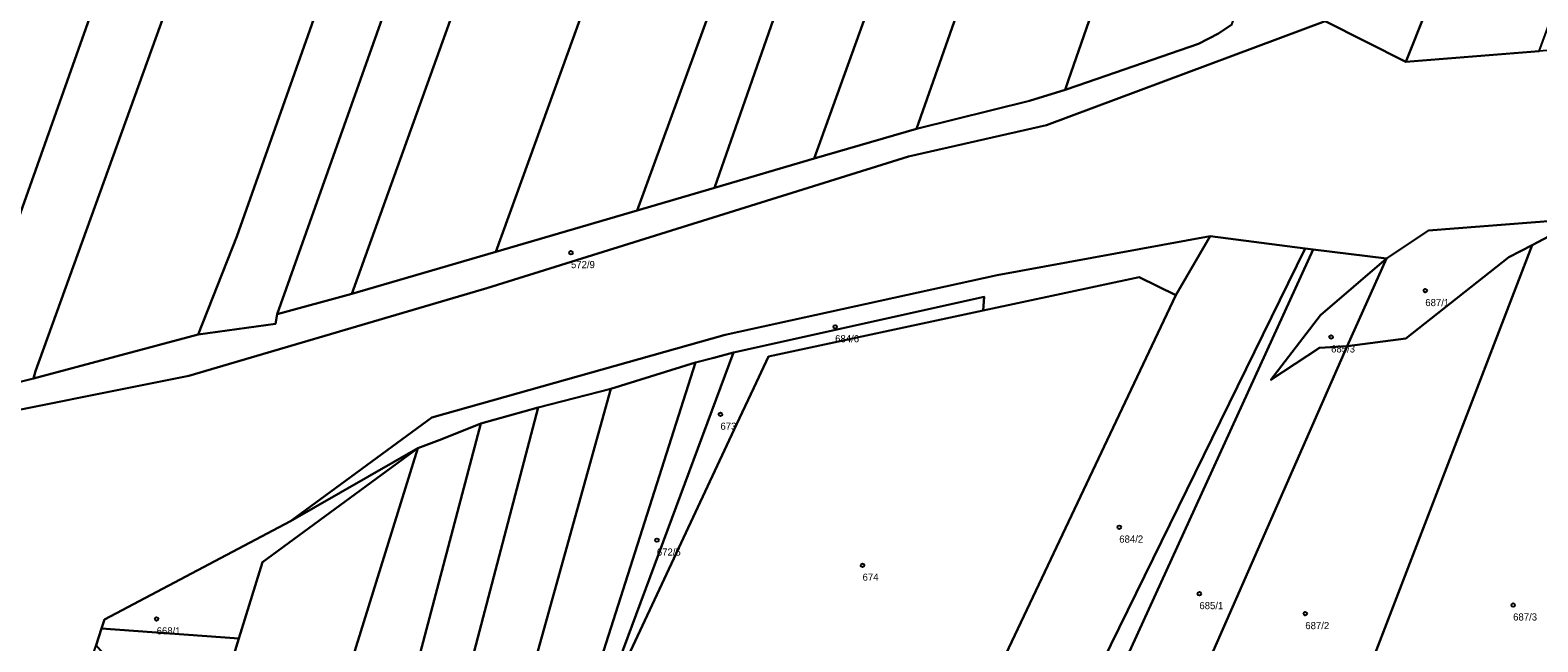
# Model space of a CAD drawing. Extents: x -587171 to -555306, y -1167727 to -1074732.
# Drawn here: x -585851.6 to -585640.5, y -1165891.7 to -1165806 of the extents above; entities that cross this region are included whole.
import ezdxf

# ---------------------------------------------------------------- set-up
doc = ezdxf.new("R2010")
doc.units = 0
doc.layers.add('Definiční body', color=7, linetype='Continuous')
doc.layers.add('Polygon parcely', color=7, linetype='Continuous')

msp = doc.modelspace()

# ---------------------------------------------------------------- linework, layer by layer
at = {"layer": 'Definiční body'}
for centre in [(-585775.86, -1165837.15), (-585656.24, -1165842.47), (-585738.87, -1165847.53), (-585669.43, -1165848.96), (-585754.93, -1165859.79), (-585699.09, -1165875.6), (-585763.83, -1165877.41), (-585735.03, -1165880.94), (-585687.87, -1165884.92), (-585643.94, -1165886.51), (-585833.87, -1165888.46), (-585673.04, -1165887.72)]:
    msp.add_circle(centre, 0.25, dxfattribs=at)
at = {"layer": 'Polygon parcely'}
for points in [[(-585806.55, -1165842.92), (-585765.04, -1165727.45), (-585762.67, -1165720.95), (-585772.03, -1165717.89), (-585777.4, -1165733.66), (-585781.47, -1165745.63), (-585816.98, -1165845.76)], [(-585816.63, -1165758.9), (-585850.85, -1165853.73), (-585851.12, -1165854.77), (-585828.07, -1165848.6), (-585822.63, -1165834.89), (-585798.71, -1165767.13), (-585790.21, -1165742.75), (-585788.68, -1165738.36), (-585788.25, -1165730.08), (-585803.96, -1165725.58), (-585805.43, -1165729.45), (-585806.58, -1165732.48), (-585811.69, -1165745.9)], [(-585763.04, -1165728.17), (-585765.04, -1165727.45), (-585806.55, -1165842.92), (-585786.4, -1165837.02), (-585753.5, -1165746.14), (-585751.18, -1165739.84), (-585749.24, -1165734.56), (-585759.82, -1165730.24), (-585760.44, -1165731.91), (-585763.85, -1165730.63)], [(-585833.2, -1165737.92), (-585839.78, -1165755.36), (-585870.01, -1165849.22), (-585861.55, -1165855.81), (-585821.32, -1165742.33)], [(-585723.27, -1165738.23), (-585729.7, -1165753.51), (-585755.78, -1165828.06), (-585741.8, -1165823.96), (-585716.86, -1165754.66), (-585712.42, -1165742.06)], [(-585706.23, -1165813.09), (-585706.66, -1165814.32), (-585704.89, -1165813.73), (-585688, -1165807.89), (-585685.18, -1165806.42), (-585683.33, -1165805.18), (-585673.14, -1165776.87), (-585661.1, -1165742.79), (-585681.23, -1165739.45), (-585682.66, -1165744.51), (-585687.44, -1165758.83), (-585689.36, -1165764.47)], [(-585811.69, -1165745.9), (-585821.32, -1165742.33), (-585861.55, -1165855.81), (-585860.03, -1165856.99), (-585851.12, -1165854.77), (-585850.85, -1165853.73), (-585816.63, -1165758.9)], [(-585816.98, -1165845.76), (-585781.47, -1165745.63), (-585790.21, -1165742.75), (-585798.71, -1165767.13), (-585822.63, -1165834.89), (-585828.07, -1165848.6), (-585817.23, -1165847.12)], [(-585786.4, -1165837.02), (-585766.58, -1165831.22), (-585737.31, -1165750.95), (-585742.04, -1165749.36), (-585747.19, -1165748.42), (-585753.5, -1165746.14)], [(-585729.7, -1165753.51), (-585737.31, -1165750.95), (-585766.58, -1165831.22), (-585755.78, -1165828.06)], [(-585741.8, -1165823.96), (-585727.47, -1165819.77), (-585706.06, -1165758.86), (-585716.86, -1165754.66)], [(-585711.66, -1165815.88), (-585706.66, -1165814.32), (-585706.23, -1165813.09), (-585689.36, -1165764.47), (-585706.06, -1165758.86), (-585727.47, -1165819.77)], [(-585658.95, -1165810.4), (-585640.31, -1165808.9), (-585627.6, -1165774.32), (-585642.37, -1165768.65)], [(-585601.64, -1165829.48), (-585634.24, -1165832.33), (-585641.27, -1165836.1), (-585677.41, -1165930.03), (-585641.63, -1165932.57)], [(-585644.54, -1165837.77), (-585641.27, -1165836.1), (-585634.24, -1165832.33), (-585655.79, -1165834.03), (-585661.69, -1165837.97), (-585667.19, -1165850.25), (-585658.98, -1165849.16)], [(-585686.38, -1165834.81), (-585716.17, -1165840.28), (-585754.28, -1165848.65), (-585795.32, -1165860.24), (-585815.11, -1165874.74), (-585797.31, -1165864.54), (-585793.94, -1165863.28), (-585788.5, -1165861.07), (-585780.43, -1165858.83), (-585770.29, -1165856.2), (-585758.41, -1165852.51), (-585755.86, -1165851.89), (-585753.12, -1165851.14), (-585718, -1165843.31), (-585718.16, -1165845.26), (-585696.32, -1165840.59), (-585691.18, -1165843.07)], [(-585716.83, -1165925.87), (-585673.05, -1165836.56), (-585686.38, -1165834.81), (-585691.18, -1165843.07), (-585725.39, -1165915.36), (-585726.06, -1165916.4), (-585729.61, -1165923.62), (-585727.83, -1165924.86), (-585724.68, -1165927.05), (-585722.13, -1165923.43), (-585718.21, -1165925.23)], [(-585671.95, -1165836.7), (-585673.05, -1165836.56), (-585716.83, -1165925.87), (-585716.21, -1165926.15), (-585715.23, -1165926.3), (-585713.03, -1165926.63)], [(-585713.03, -1165926.63), (-585701.5, -1165928.37), (-585667.19, -1165850.25), (-585671.06, -1165850.48), (-585677.87, -1165854.93), (-585670.92, -1165845.89), (-585661.69, -1165837.97), (-585671.95, -1165836.7)], [(-585697.2, -1165928.65), (-585677.41, -1165930.03), (-585641.27, -1165836.1), (-585644.54, -1165837.77), (-585658.98, -1165849.16), (-585667.19, -1165850.25), (-585701.5, -1165928.37)], [(-585667.19, -1165850.25), (-585661.69, -1165837.97), (-585670.92, -1165845.89), (-585677.87, -1165854.93), (-585671.06, -1165850.48)], [(-585725.39, -1165915.36), (-585691.18, -1165843.07), (-585696.32, -1165840.59), (-585718.16, -1165845.26), (-585748.18, -1165851.68), (-585750.24, -1165856.07), (-585752.66, -1165861.23), (-585768.55, -1165895.15), (-585769.07, -1165896.34), (-585755.79, -1165902.5), (-585741.34, -1165909.22), (-585726.06, -1165916.4)], [(-585718.16, -1165845.26), (-585718, -1165843.31), (-585753.12, -1165851.14), (-585769.78, -1165896.02), (-585769.07, -1165896.34), (-585768.55, -1165895.15), (-585752.66, -1165861.23), (-585750.24, -1165856.07), (-585748.18, -1165851.68)], [(-585792.84, -1165937.27), (-585784.8, -1165938.96), (-585771.98, -1165895.04), (-585758.41, -1165852.51), (-585770.29, -1165856.2)], [(-585755.86, -1165851.89), (-585758.41, -1165852.51), (-585771.98, -1165895.04), (-585769.78, -1165896.02), (-585753.12, -1165851.14)], [(-585770.29, -1165856.2), (-585780.43, -1165858.83), (-585800.62, -1165935.76), (-585792.84, -1165937.27)], [(-585780.43, -1165858.83), (-585788.5, -1165861.07), (-585807.21, -1165931.95), (-585800.62, -1165935.76)], [(-585793.94, -1165863.28), (-585797.31, -1165864.54), (-585805.95, -1165892.32), (-585815.17, -1165922.86), (-585807.21, -1165931.95), (-585788.5, -1165861.07)], [(-585822.34, -1165891.19), (-585819.07, -1165880.5), (-585797.31, -1165864.54), (-585815.11, -1165874.74), (-585841.17, -1165888.52), (-585841.6, -1165889.8)], [(-585819.07, -1165880.5), (-585822.34, -1165891.19), (-585827.76, -1165908.87), (-585815.17, -1165922.86), (-585805.95, -1165892.32), (-585797.31, -1165864.54)], [(-585827.76, -1165908.87), (-585822.34, -1165891.19), (-585841.6, -1165889.8), (-585842.32, -1165892.13)]]:
    msp.add_lwpolyline(points, close=True, dxfattribs=at)
for points in [[(-585670.26, -1165804.71), (-585658.95, -1165810.4), (-585642.37, -1165768.65)], [(-585596.77, -1165805.42), (-585619.73, -1165807.2), (-585625.24, -1165807.66), (-585640.31, -1165808.9), (-585658.95, -1165810.4), (-585670.26, -1165804.71), (-585709.26, -1165819.29), (-585728.59, -1165823.68), (-585787.62, -1165842.09), (-585829.37, -1165854.4), (-585862.52, -1165861.01), (-585867.08, -1165863.32), (-585880.42, -1165869.92), (-585924.13, -1165898.32), (-586016.63, -1165942.03), (-586047.1, -1165956.01)], [(-585862.52, -1165861.01), (-585829.37, -1165854.4), (-585787.62, -1165842.09), (-585728.59, -1165823.68), (-585709.26, -1165819.29), (-585670.26, -1165804.71)], [(-585683.33, -1165805.18), (-585685.18, -1165806.42), (-585688, -1165807.89), (-585704.89, -1165813.73), (-585706.66, -1165814.32), (-585711.66, -1165815.88), (-585727.47, -1165819.77), (-585741.8, -1165823.96), (-585755.78, -1165828.06), (-585766.58, -1165831.22), (-585786.4, -1165837.02), (-585806.55, -1165842.92), (-585816.98, -1165845.76), (-585817.23, -1165847.12), (-585828.07, -1165848.6), (-585851.12, -1165854.77), (-585860.03, -1165856.99)], [(-585870.27, -1165898.87), (-585850.05, -1165893.53), (-585847.15, -1165894.58), (-585844.03, -1165897.09), (-585842.32, -1165892.13), (-585841.6, -1165889.8), (-585841.17, -1165888.52), (-585815.11, -1165874.74), (-585795.32, -1165860.24), (-585754.28, -1165848.65), (-585716.17, -1165840.28), (-585686.38, -1165834.81), (-585673.05, -1165836.56), (-585671.95, -1165836.7), (-585661.69, -1165837.97), (-585655.79, -1165834.03), (-585634.24, -1165832.33), (-585601.64, -1165829.48), (-585574.23, -1165827.48), (-585571.06, -1165827.26), (-585554.63, -1165826.13), (-585538.56, -1165825.04), (-585509.22, -1165823.03)]]:
    msp.add_lwpolyline(points, dxfattribs=at)

# ---------------------------------------------------------------- texts
at = {"layer": 'Definiční body'}
for s, p in [('572/9', (-585775.86, -1165839.31)), ('687/1', (-585656.24, -1165844.63)), ('684/6', (-585738.87, -1165849.69)), ('685/3', (-585669.43, -1165851.12)), ('673', (-585754.93, -1165861.95)), ('684/2', (-585699.09, -1165877.76)), ('672/5', (-585763.83, -1165879.57)), ('674', (-585735.03, -1165883.1)), ('685/1', (-585687.87, -1165887.08)), ('687/3', (-585643.94, -1165888.67)), ('668/1', (-585833.87, -1165890.62)), ('687/2', (-585673.04, -1165889.88))]:
    msp.add_text(s, height=1, dxfattribs=at).set_placement(p)

doc.saveas('drawing.dxf')
